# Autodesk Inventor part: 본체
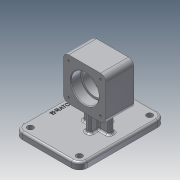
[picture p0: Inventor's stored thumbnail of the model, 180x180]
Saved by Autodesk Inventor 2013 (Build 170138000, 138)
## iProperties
Created: 2020-11
Part Number: 본체
Material: 알루미늄 6061
Document SubType Name: Modeling
Designer: user
Density: 2.71 g/cm^3
Mass: 685.719 g
Surface Area: 548.419 cm^2
Volume: 253.033 cm^3
Author: user
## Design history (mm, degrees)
sketch "스케치1"
  geometry: L1 (-32, -32)-(32, -32); L2 (32, -32)-(32, 32); L3 (32, 32)-(-32, 32); L4 (-32, 32)-(-32, -32); L5 (-32, -32)-(32, 32); L6 (32, -32)-(-32, 32); 1 further point
  constraints: 12 end point, 2 midpoint, 2 parallel, 1 horizontal, 1 perpendicular
  dimensions: "d0" = 64 distance of L3.end L2.end; "d1" = 64 distance of L2.end L1.end
extrude "돌출1" new body sketch "스케치1" stored distance "d2" = 42; taper "d3" = 0 deg
sketch "스케치2"
  geometry: L1 (32, -21)-(-32, -21) reference; L2 (-32, -21)-(-32, 21) reference; L3 (-32, 21)-(32, 21) reference; L4 (32, 21)-(32, -21) reference; L5 (0, 21)-(0, -21); L6 (0, 21)-(21, 21); L7 (21, 21)-(21, 6); L8 (21, 6)-(18, 6); L9 (18, 6)-(18, -6); L10 (18, -6)-(21, -6); L11 (21, -6)-(21, -21); L12 (21, -21)-(0, -21); 1 further point
  constraints: 16 end point, 4 perpendicular, 2 midpoint, 2 point on line, 1 collinear, 1 parallel
  dimensions: "d4" = 15 distance between parallel lines of L8 L6; "d6" = 15 distance between parallel lines of L1 L10; "d7" = 36 diameter of L9 L5; "d8" = 42 diameter of L11 L5; "d9" = 42 diameter of L7 L5
revolve "회전1" sketch "스케치2" stored, may be unused: angle "d10" = 90 deg
sketch "스케치3"
  geometry: A1 r 8 centre (24, -24) between (24, -32) and (32, -24) reference; A2 r 8 centre (24, 24) between (32, 24) and (24, 32) reference; A3 r 8 centre (-24, 24) between (-24, 32) and (-32, 24) reference; A4 r 8 centre (-24, -24) between (-32, -24) and (-24, -32) reference; 4 further points
  constraints: 4 coincident
hole "구멍1" sketch "스케치3" at (-24, 24), (24, 24), (24, -24), (-24, -24) diameter "d12" = 3.242; stored, may be unused: countersink angle "d16" = 90 deg, drill point angle "d18" = 118 deg; dims "d13" = 8, "d14" = 4, "d15" = 2, "d17" = 10
node "작업 평면1"
sketch "스케치8"
  geometry: L1 (-32, -21)-(-32, 21) reference; L2 (32, -21)-(32, 21) reference; L3 (62, 65)-(-36, 65); L4 (-36, 65)-(-36, -65); L5 (-36, -65)-(62, -65); L6 (62, -65)-(62, 65); 2 further points
  constraints: 8 end point, 2 parallel, 1 horizontal, 1 horizontal alignment, 1 midpoint, 1 perpendicular
  dimensions: "d38" = 98 distance of L5.end L4.end; "d39" = 130 distance of L4.end L3.end; "d40" = 36 distance from line of L4 point (0, 0)
extrude "돌출5" join sketch "스케치8" distance "d41" = 10; taper "d42" = 0 deg
sketch "스케치9"
  geometry: L1 (-62, 65)-(-62, -65) reference; L2 (-20, -4)-(20, -4); L3 (20, -4)-(20, 4); L4 (20, 4)-(-20, 4); L5 (-20, 4)-(-20, -4); L6 (0, -4)-(0, 4); L7 (-62, 65)-(-62, -65) reference; L8 (-4, -17)-(4, -17); L9 (4, -17)-(4, 17); L10 (4, 17)-(-4, 17); L11 (-4, 17)-(-4, -17); L12 (0, -17)-(0, 17); L13 (-4, 0)-(4, 0); 3 further points
  constraints: 22 end point, 8 midpoint, 4 parallel, 3 perpendicular, 2 horizontal, 2 horizontal alignment
  dimensions: "d43" = 40 distance of L4.end L3.end; "d44" = 8 distance of L3.end L2.end; "d45" = 62 distance between parallel lines of L6 L1; "d48" = 8 distance of L10.end L9.end; "d49" = 34 distance of L9.end L8.end; "d50" = 62 distance between parallel lines of L12 L1
extrude "돌출6" join sketch "스케치9" stored distance "d51" = 0; taper "d52" = 0 deg
fillet "모깎기2" dims "d53" = 8
fillet "모깎기3" dims "d54" = 12
sketch "스케치10"
  geometry: C1 r 4.5 at (-50, -53); C2 r 4.5 at (-50, 53); C3 r 4.5 at (24, 53); C4 r 4.5 at (24, -53); A1 r 12 centre (24, -53) between (24, -65) and (36, -53) reference; A2 r 12 centre (24, 53) between (36, 53) and (24, 65) reference; A3 r 12 centre (-50, 53) between (-50, 65) and (-62, 53) reference; A4 r 12 centre (-50, -53) between (-62, -53) and (-50, -65) reference; 1 further point
  constraints: 4 centre point, 4 coincident
  dimensions: "d55" = 9 diameter of C1; "d56" = 9 diameter of C2; "d57" = 9 diameter of C3; "d58" = 9 diameter of C4
extrude "돌출7" cut sketch "스케치10" distance "d59" = 9 (= d55); taper "d60" = 0 deg
sketch "스케치11"
  geometry: L1 (24, 65)-(-50, 65) reference; L2 (-62, 53)-(-62, -53) reference; 2 further points
  constraints: 1 other
  dimensions: "d61" = 65 distance from line of point (-52, 0) L1; "d62" = 10 distance from line of point (-52, 0) L2
feature "엠보싱1" sketch "스케치11" dims "d63" = 0.5, "d64" = 0
fillet "모깎기4" dims "d65" = 0.3
chamfer "모따기1" distance "d66" = 1; stored, may be unused: second distance "d67" = 2, angle "d68" = 45 deg
fillet "모깎기5" dims "d69" = 3
fillet "모깎기6" dims "d70" = 3
fillet "모깎기7" dims "d71" = 3
node "솔리드1"
mirror "대칭1"
node "절단 모서리 투영1"
